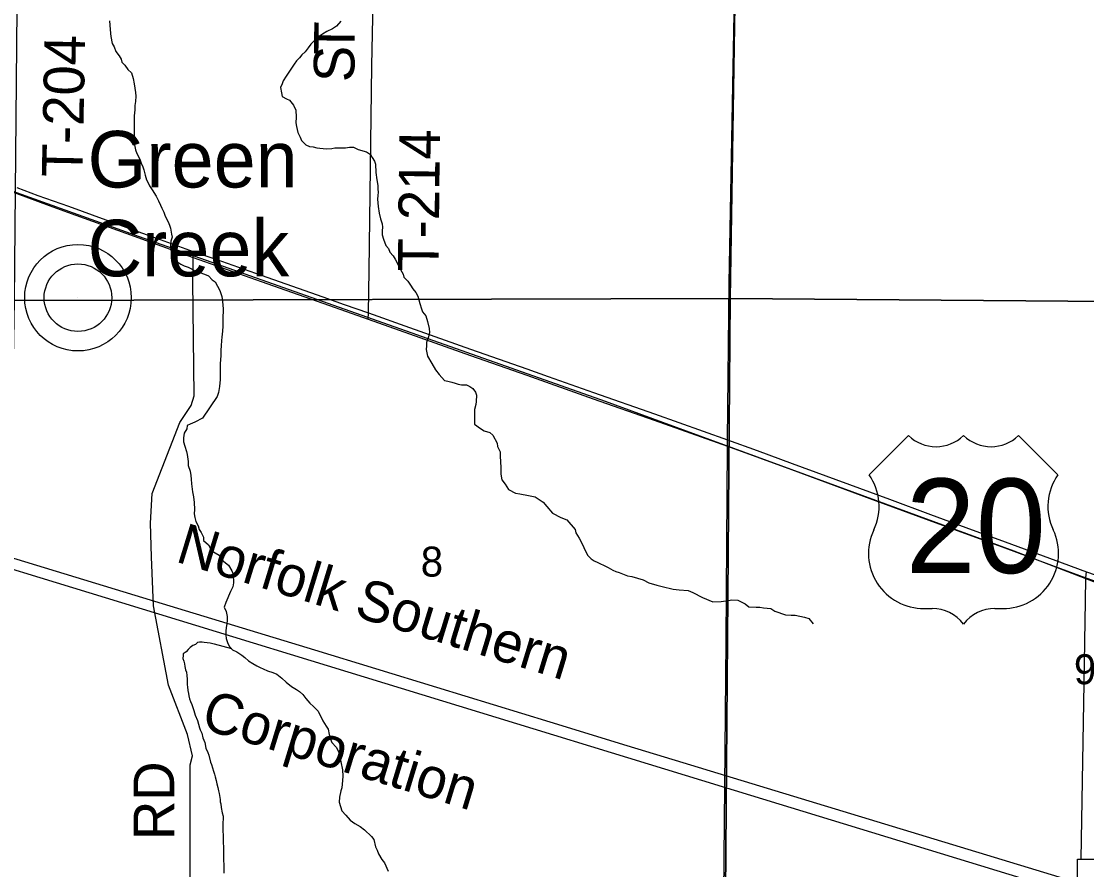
# Model space of a CAD drawing. Extents: x 0 to 34, y 0 to 22.
# Drawn here: x 27.011 to 28.499, y 18.124 to 19.309 of the extents above; entities that cross this region are included whole.
import ezdxf

# ---------------------------------------------------------------- set-up
doc = ezdxf.new("R2010")
doc.units = 0
for name, color, linetype in [('GM_X_Minor_River', 7, 'Continuous'), ('GM_X_Rail_Line', 7, 'Continuous'), ('GM_X_Rail_Line_Text', 7, 'Continuous'), ('GM_X_Section', 7, 'Continuous'), ('GM_X_Section_Text', 7, 'Continuous'), ('GM_X_Township_Road', 7, 'Continuous'), ('GM_X_Township_Road_Text', 7, 'Continuous'), ('GM_X_Unincorporated', 7, 'Continuous'), ('GM_X_Unincorporated_Location', 7, 'Continuous'), ('GM_X_Unincorporated_Text', 7, 'Continuous'), ('GM_X_US_Route', 7, 'Continuous'), ('GM_X_US_Shield', 7, 'Continuous'), ('SH_Data', 7, 'Continuous')]:
    doc.layers.add(name, color=color, linetype=linetype)

msp = doc.modelspace()

# ---------------------------------------------------------------- linework, layer by layer
at = {"layer": 'GM_X_Minor_River'}
for points in [[(27.134, 19.3097), (27.1344, 19.3036), (27.1354, 19.2922), (27.1357, 19.288), (27.1375, 19.2781), (27.1401, 19.2736), (27.1427, 19.2671), (27.1475, 19.2609), (27.1501, 19.2564), (27.1508, 19.2522), (27.155, 19.248), (27.1594, 19.2418), (27.1643, 19.2372), (27.1669, 19.2292), (27.1683, 19.2216), (27.1694, 19.2155), (27.1701, 19.2098), (27.1704, 19.2045), (27.1699, 19.1969)], [(27.4569, 19.3092), (27.4507, 19.3021), (27.4454, 19.2984), (27.4374, 19.2947), (27.4312, 19.2913), (27.4259, 19.2872), (27.4217, 19.2838), (27.4151, 19.2771), (27.4113, 19.2718), (27.4071, 19.2665), (27.4025, 19.2624), (27.399, 19.2582), (27.3952, 19.2537), (27.3917, 19.2492), (27.3844, 19.2379), (27.3805, 19.2326), (27.3766, 19.2258), (27.3751, 19.2217), (27.3727, 19.2168), (27.3742, 19.2092), (27.3752, 19.2042), (27.3809, 19.2007), (27.3854, 19.1988), (27.3907, 19.1919), (27.394, 19.1847), (27.3946, 19.1752), (27.3942, 19.1672), (27.3949, 19.1623), (27.397, 19.1539), (27.4, 19.1474), (27.4022, 19.1424), (27.4079, 19.1363), (27.4131, 19.1343), (27.4181, 19.1335), (27.4234, 19.1323), (27.4366, 19.1311), (27.4446, 19.1313), (27.4488, 19.1321), (27.4529, 19.1324), (27.4636, 19.1323), (27.4693, 19.1334), (27.4746, 19.1333), (27.4814, 19.1302), (27.4927, 19.1267), (27.4984, 19.1228), (27.5006, 19.1186), (27.5039, 19.1136), (27.5054, 19.1094), (27.506, 19.098), (27.5074, 19.0878), (27.5089, 19.0798), (27.5088, 19.0745), (27.5091, 19.0703), (27.5087, 19.0658), (27.5083, 19.0604), (27.5086, 19.0555), (27.5093, 19.0502), (27.5103, 19.0411), (27.5125, 19.0331), (27.5147, 19.0262), (27.5154, 19.0213), (27.5146, 19.0163), (27.5149, 19.0106), (27.5164, 19.0049), (27.5197, 18.9958), (27.5234, 18.9916), (27.5256, 18.9866), (27.5301, 18.9813), (27.5331, 18.9767), (27.5357, 18.9717), (27.5387, 18.9656), (27.5442, 18.956), (27.545, 18.9515), (27.5506, 18.9461), (27.5543, 18.9404), (27.5577, 18.9354), (27.5618, 18.93), (27.5644, 18.9251), (27.5658, 18.9201), (27.5673, 18.9148), (27.5695, 18.9076), (27.5713, 18.9034), (27.5758, 18.8976), (27.578, 18.8896), (27.5802, 18.8797), (27.5809, 18.8744), (27.5793, 18.8684), (27.5765, 18.8604), (27.5765, 18.8555), (27.576, 18.8506), (27.5782, 18.8414), (27.5842, 18.8311), (27.5894, 18.8223), (27.5942, 18.8154), (27.6017, 18.8074)], [(27.1699, 19.1969), (27.1691, 19.1913), (27.169, 19.1852), (27.1682, 19.1768), (27.1684, 19.1639), (27.1682, 19.1442), (27.1689, 19.1366), (27.1703, 19.1294), (27.1721, 19.1244), (27.1762, 19.1164), (27.1781, 19.1111), (27.1803, 19.1057), (27.1817, 19.1015), (27.1836, 19.0943), (27.1854, 19.0874), (27.1876, 19.0832), (27.1895, 19.0791), (27.1936, 19.0737), (27.1988, 19.0649), (27.2021, 19.0584), (27.2051, 19.0523), (27.2069, 19.0481), (27.2095, 19.0424), (27.2117, 19.0367), (27.2158, 19.0287), (27.2177, 19.0241), (27.2191, 19.0199), (27.2202, 19.0119), (27.2213, 19.0077), (27.2193, 19.0021), (27.2188, 18.9941), (27.2199, 18.9869), (27.2206, 18.9823), (27.2236, 18.977), (27.2277, 18.9735), (27.2333, 18.9696), (27.2383, 18.9673), (27.2435, 18.9657), (27.2492, 18.9626), (27.2556, 18.9588), (27.2601, 18.958), (27.2666, 18.9556), (27.2719, 18.9533), (27.2771, 18.9479), (27.2812, 18.9452), (27.2846, 18.9391), (27.2879, 18.933), (27.2905, 18.9246), (27.2916, 18.9178), (27.2926, 18.9075), (27.2925, 18.9033), (27.2921, 18.8973), (27.2919, 18.8832), (27.2915, 18.876), (27.2906, 18.8677), (27.2902, 18.8631), (27.2897, 18.8555), (27.2893, 18.8498), (27.2892, 18.8423), (27.2887, 18.8362), (27.2883, 18.8309), (27.2882, 18.8259), (27.2885, 18.8191), (27.2884, 18.8085), (27.2875, 18.799), (27.2863, 18.7903), (27.2843, 18.785)], [(27.6017, 18.8074), (27.6063, 18.8062), (27.6119, 18.805), (27.6165, 18.8034), (27.621, 18.8023), (27.6256, 18.8014), (27.6324, 18.801), (27.6373, 18.799), (27.6414, 18.796), (27.6452, 18.791), (27.6466, 18.7868), (27.6461, 18.7777), (27.6457, 18.7735), (27.6437, 18.7667), (27.6436, 18.7508), (27.6439, 18.7462), (27.6522, 18.74), (27.6574, 18.737), (27.665, 18.7346), (27.6691, 18.7311), (27.6755, 18.7197), (27.6758, 18.7151), (27.6795, 18.7075), (27.6798, 18.7029), (27.6801, 18.6923), (27.6804, 18.687), (27.6803, 18.6817), (27.6806, 18.6764), (27.6821, 18.6684), (27.6866, 18.6626), (27.691, 18.655), (27.7008, 18.6499), (27.7069, 18.6491), (27.719, 18.6467), (27.7285, 18.6447), (27.7398, 18.6374), (27.7446, 18.6313), (27.7529, 18.6221), (27.7645, 18.6159), (27.7725, 18.6127), (27.7845, 18.5989), (27.7855, 18.5944), (27.79, 18.5871), (27.7934, 18.581), (27.7996, 18.5669), (27.8019, 18.5627), (27.8067, 18.5581), (27.8109, 18.5554), (27.8158, 18.5531), (27.8199, 18.5511), (27.8241, 18.5492), (27.8305, 18.5461), (27.8369, 18.5422), (27.8411, 18.5406), (27.8456, 18.5391), (27.8573, 18.5344), (27.8637, 18.5332), (27.8792, 18.5288), (27.8872, 18.5246), (27.8985, 18.5214), (27.9061, 18.5194), (27.9212, 18.5159), (27.9295, 18.5146), (27.942, 18.5137), (27.9488, 18.511), (27.9624, 18.504), (27.9768, 18.4982), (27.9881, 18.4984), (27.9988, 18.4998), (28.003, 18.5006), (28.0117, 18.5005), (28.0219, 18.4954), (28.0268, 18.4912), (28.0374, 18.4907), (28.0423, 18.4907), (28.0476, 18.4895), (28.0578, 18.4886), (28.0635, 18.4851), (28.0782, 18.48), (28.0862, 18.4796), (28.0915, 18.4795), (28.1047, 18.4767), (28.1108, 18.4747), (28.1168, 18.4671)], [(27.2843, 18.785), (27.2639, 18.7548), (27.2532, 18.7489), (27.2467, 18.7463), (27.2425, 18.7445), (27.2417, 18.7399), (27.2382, 18.7335), (27.237, 18.7271), (27.237, 18.7214), (27.2392, 18.7153), (27.2414, 18.708), (27.2424, 18.7038), (27.2435, 18.6943), (27.2438, 18.6886), (27.2464, 18.6806), (27.2474, 18.6746), (27.2477, 18.6692), (27.2484, 18.6628), (27.2498, 18.6518), (27.2513, 18.6449), (27.2523, 18.6369), (27.2526, 18.6271), (27.2521, 18.621), (27.2532, 18.616), (27.2543, 18.6103), (27.2576, 18.6042), (27.2591, 18.5993), (27.2617, 18.5947), (27.265, 18.5882), (27.2653, 18.5836), (27.2721, 18.5775), (27.2769, 18.5691), (27.2815, 18.5664), (27.2871, 18.5633), (27.2912, 18.5564), (27.2999, 18.5491), (27.3047, 18.5415), (27.3065, 18.5365), (27.3072, 18.5247), (27.3063, 18.5191), (27.3028, 18.5126), (27.2962, 18.4972), (27.2939, 18.4907), (27.2968, 18.4846), (27.2983, 18.4774), (27.2982, 18.4721), (27.2978, 18.4671), (27.297, 18.4622), (27.2965, 18.4569), (27.2965, 18.4516), (27.2968, 18.4467), (27.2986, 18.4413), (27.3012, 18.436), (27.3057, 18.431), (27.3117, 18.4283), (27.3185, 18.4233), (27.3227, 18.4202), (27.3279, 18.4156), (27.3339, 18.4117), (27.3396, 18.4086), (27.3445, 18.4063), (27.3486, 18.4044), (27.3547, 18.4016), (27.3619, 18.3993), (27.3675, 18.3969), (27.3747, 18.3915), (27.3807, 18.3858), (27.3882, 18.3796), (27.395, 18.3754), (27.3991, 18.3727), (27.404, 18.3685), (27.4081, 18.3631), (27.4137, 18.3566), (27.419, 18.3516), (27.4254, 18.3455), (27.4316, 18.3317), (27.4365, 18.3245), (27.4395, 18.3203), (27.4405, 18.3127), (27.442, 18.3077), (27.4442, 18.3016), (27.4506, 18.2951), (27.4535, 18.289), (27.4554, 18.2825), (27.4568, 18.2745), (27.4593, 18.2635), (27.46, 18.2547), (27.4595, 18.2483), (27.4583, 18.2381), (27.4571, 18.2339), (27.4551, 18.2252), (27.4546, 18.218), (27.4583, 18.2062), (27.4639, 18.2), (27.4699, 18.1928), (27.4767, 18.1885), (27.4842, 18.1843), (27.4902, 18.1796), (27.4996, 18.1704), (27.503, 18.1658), (27.5055, 18.1556)], [(27.3045, 18.4324), (27.2807, 18.4387), (27.2781, 18.4395), (27.2743, 18.4403), (27.266, 18.4413), (27.2634, 18.4417), (27.2596, 18.4418), (27.2569, 18.4411), (27.2538, 18.4385), (27.2504, 18.437), (27.2466, 18.4344), (27.2439, 18.4315), (27.2408, 18.4281), (27.2369, 18.4255), (27.2365, 18.4229), (27.2364, 18.4187), (27.2375, 18.4153), (27.2385, 18.4115), (27.2392, 18.4077), (27.2399, 18.4031), (27.2413, 18.4), (27.2416, 18.3951), (27.2422, 18.3902), (27.2422, 18.3875), (27.2425, 18.3822), (27.2428, 18.3791), (27.2434, 18.3742), (27.2441, 18.37), (27.2448, 18.3666), (27.2454, 18.3624), (27.2469, 18.359), (27.2487, 18.3544), (27.2515, 18.346), (27.2537, 18.3395), (27.2566, 18.3322), (27.2583, 18.3272), (27.2594, 18.3219), (27.2604, 18.3192), (27.2626, 18.3146), (27.2644, 18.3082), (27.2669, 18.3017), (27.2686, 18.2937), (27.2711, 18.2875), (27.2726, 18.2837), (27.2747, 18.2742), (27.2761, 18.2708), (27.2779, 18.2662), (27.2789, 18.2616), (27.2804, 18.2574), (27.2814, 18.2536), (27.2828, 18.2486), (27.2839, 18.2437), (27.2853, 18.2387), (27.2863, 18.2341), (27.287, 18.2303), (27.2883, 18.222), (27.2886, 18.2185), (27.2893, 18.2159), (27.29, 18.2105), (27.2913, 18.2033), (27.2924, 18.1984), (27.2921, 18.1855), (27.2923, 18.1775), (27.2926, 18.1722), (27.2925, 18.1669), (27.2928, 18.1623), (27.293, 18.1547), (27.2929, 18.1494), (27.293, 18.1392), (27.293, 18.1354), (27.2933, 18.1327), (27.2937, 18.1191)], [(27.5055, 18.1556), (27.5077, 18.151), (27.5096, 18.146), (27.5144, 18.138), (27.5178, 18.1334), (27.5229, 18.1216)]]:
    msp.add_lwpolyline(points, dxfattribs=at)
at = {"layer": 'GM_X_Rail_Line'}
for points in [[(24.6857, 19.9193), (25.0148, 19.7985), (25.4772, 19.6296), (26.0332, 19.4244), (26.618, 19.2083), (27.1754, 19.0083), (27.8265, 18.7785), (28.397, 18.5695), (29.2915, 18.2251), (29.5147, 18.1387)], [(24.1704, 19.5327), (24.2425, 19.4909), (24.3878, 19.4135), (24.5787, 19.3195), (24.7175, 19.2589), (24.8405, 19.2105), (24.9746, 19.1639), (25.4423, 19.0168), (26.3104, 18.7542), (27.1506, 18.4971), (27.9899, 18.2401), (28.4862, 18.088)], [(26.9875, 18.5627), (27.1965, 18.4991), (27.42, 18.4308), (27.5908, 18.3787), (27.749, 18.3302), (27.8567, 18.2973), (27.9349, 18.2735), (27.9943, 18.2554), (28.4862, 18.1059)]]:
    msp.add_lwpolyline(points, dxfattribs=at)
at = {"layer": 'GM_X_Section'}
for points in [[(29.0105, 19.8743), (29.0034, 18.9139), (28.001, 18.9217), (28.0159, 19.8585), (28.0523, 19.8602)], [(28.0159, 19.8585), (28.001, 18.9217), (27.0012, 18.9192), (27.0095, 19.8363), (27.044, 19.8365)], [(28.001, 18.9217), (27.9928, 17.9132), (26.984, 17.9172), (27.0012, 18.9192)]]:
    msp.add_lwpolyline(points, close=True, dxfattribs=at)
msp.add_lwpolyline([(28.4862, 17.9139), (27.9928, 17.9132), (28.001, 18.9217), (29.0034, 18.9139), (28.9945, 18.1387)], dxfattribs=at)
at = {"layer": 'GM_X_Township_Road'}
msp.add_line((27.9854, 17.4096), (27.9934, 18.2405), dxfattribs=at)
for points in [[(27.4952, 18.8928), (27.4954, 18.9016), (27.4964, 18.961), (27.5002, 19.2468), (27.504, 19.4276)], [(27.9971, 18.7155), (27.9972, 18.7243), (27.9997, 18.9437), (28.0083, 19.4207)], [(27.2506, 18.9693), (27.2507, 18.9792), (27.2509, 18.9877)], [(27.1953, 18.4923), (27.1926, 18.5607), (27.1911, 18.6078), (27.1933, 18.6496), (27.2321, 18.7485), (27.2481, 18.7721), (27.2521, 18.7858), (27.2502, 18.9463), (27.2506, 18.9693)], [(27.9934, 18.2405), (27.9954, 18.4433), (27.9971, 18.7155)], [(28.4965, 18.4429), (28.4972, 18.4985), (28.4979, 18.5316), (28.4986, 18.5401)], [(27.2521, 17.6804), (27.2543, 17.9349), (27.2463, 17.9776), (27.2464, 18.2704), (27.2497, 18.2829), (27.2429, 18.3126), (27.216, 18.3814), (27.1953, 18.4923)], [(28.4915, 18.1387), (28.4961, 18.4121), (28.4965, 18.4429)]]:
    msp.add_lwpolyline(points, dxfattribs=at)
at = {"layer": 'GM_X_Unincorporated'}
for radius in [0.0744, 0.0472]:
    msp.add_circle((27.0897, 18.9229), radius, dxfattribs=at)
at = {"layer": 'GM_X_Unincorporated_Location'}
msp.add_line((27.0897, 18.9229), (27.0897, 18.9229), dxfattribs=at)
at = {"layer": 'GM_X_US_Route'}
for points in [[(26.7863, 19.1468), (26.8121, 19.1376), (26.9472, 19.0885), (27.0041, 19.0684), (27.0497, 19.0517)], [(27.0042, 19.0768), (27.0338, 19.0659), (27.0763, 19.0506), (27.1619, 19.0197), (27.2046, 19.0042), (27.2509, 18.9877), (27.2902, 18.9738), (27.3459, 18.9544), (27.4319, 18.924), (27.4616, 18.9134), (27.4954, 18.9016)], [(27.0497, 19.0517), (27.0753, 19.0424), (27.1682, 19.0089), (27.2507, 18.9792), (27.3458, 18.9456), (27.4318, 18.9152), (27.4952, 18.8928)], [(27.4952, 18.8928), (27.5529, 18.8725), (27.638, 18.8424), (27.7169, 18.8146), (27.8097, 18.7818), (27.8949, 18.7519), (27.9971, 18.7155)], [(27.4954, 18.9016), (27.553, 18.8813), (27.6381, 18.8512), (27.717, 18.8234), (27.7468, 18.8127), (27.8098, 18.7906), (27.895, 18.7607), (27.9972, 18.7243)], [(27.9972, 18.7243), (28.0386, 18.7093), (28.0875, 18.6912), (28.1814, 18.6568), (28.2235, 18.6413), (28.2808, 18.6202), (28.33, 18.6021), (28.3853, 18.5817), (28.4645, 18.5527), (28.4986, 18.5401), (28.5214, 18.5318), (28.562, 18.5169), (28.6051, 18.5011), (28.6487, 18.485), (28.6914, 18.469), (28.7198, 18.4578), (28.7392, 18.4501), (28.7759, 18.4356), (28.8173, 18.4191), (28.909, 18.3828), (29.0076, 18.3435), (29.0917, 18.3102), (29.1829, 18.2741), (29.2048, 18.2652)], [(27.9971, 18.7155), (28.0868, 18.6828), (28.1999, 18.6412), (28.2925, 18.6071), (28.3847, 18.5733), (28.4626, 18.5445), (28.4979, 18.5316), (28.5192, 18.5239), (28.5618, 18.5082), (28.6048, 18.4923), (28.647, 18.4766), (28.6897, 18.4603), (28.7188, 18.4491), (28.739, 18.4414), (28.8158, 18.4109), (28.9075, 18.3747), (29.0061, 18.3354), (29.0902, 18.3021), (29.1814, 18.2659), (29.2033, 18.2571)]]:
    msp.add_lwpolyline(points, dxfattribs=at)
at = {"layer": 'GM_X_US_Shield'}
for p, q in [((28.25, 18.7305), (28.1951, 18.6756)), ((28.4587, 18.6756), (28.4038, 18.7305)), ((28.272, 18.4888), (28.283, 18.4888)), ((28.3708, 18.4888), (28.3818, 18.4888))]:
    msp.add_line(p, q, dxfattribs=at)
for centre, radius, start, end in [((28.2885, 18.7697), 0.0549, 225.573, 314.427), ((28.3654, 18.7697), 0.0549, 225.573, 314.427), ((28.1321, 18.6315), 0.0769, 334.5471, 35.0009), ((28.5217, 18.6315), 0.0769, 144.9991, 205.4529), ((28.2711, 18.5657), 0.0769, 154.8319, 270.6383), ((28.3827, 18.5657), 0.0769, 269.3617, 25.1681), ((28.283, 18.4339), 0.0549, 36.8699, 90), ((28.3708, 18.4339), 0.0549, 90, 143.1301)]:
    msp.add_arc(centre, radius, start, end, dxfattribs=at)
at = {"layer": 'SH_Data'}
msp.add_lwpolyline([(28.4862, 18.1387), (29.9962, 18.1387), (29.9962, 17.4387), (28.4862, 17.4387)], close=True, dxfattribs=at)

# ---------------------------------------------------------------- texts
at = {"layer": 'GM_X_Rail_Line_Text'}
for s, rotation, p in [('Norfolk Southern', 342.9781, (27.2244, 18.5547)), ('Corporation', 343.0149, (27.2594, 18.3219))]:
    msp.add_text(s, height=0.056629, rotation=rotation, dxfattribs=at).set_placement(p)
at = {"layer": 'GM_X_Section_Text'}
for s, p in [('8', (27.5686, 18.5333)), ('9', (28.4811, 18.3829))]:
    msp.add_text(s, height=0.0419, rotation=0, dxfattribs=at).set_placement(p)
at = {"layer": 'GM_X_Township_Road_Text'}
for s, height, rotation, p in [('T', 0.0568, 89.4257, (27.4762, 19.2622)), ('T-204', 0.05682, 88.8762, (27.096, 19.0909)), ('S', 0.0568, 89.4251, (27.4758, 19.2239)), ('T-214', 0.05682, 89.4386, (27.5935, 18.9593)), ('RD', 0.05682, 90, (27.2242, 18.1653))]:
    msp.add_text(s, height=height, rotation=rotation, dxfattribs=at).set_placement(p)
at = {"layer": 'GM_X_Unincorporated_Text'}
for s, p in [('Green', (27.1032, 19.0769)), ('Creek', (27.1032, 18.9528))]:
    msp.add_text(s, height=0.07898, rotation=0, dxfattribs=at).set_placement(p)
at = {"layer": 'GM_X_US_Shield'}
msp.add_text('20', height=0.13184, dxfattribs=at).set_placement((28.246, 18.5383))

doc.saveas('drawing.dxf')
